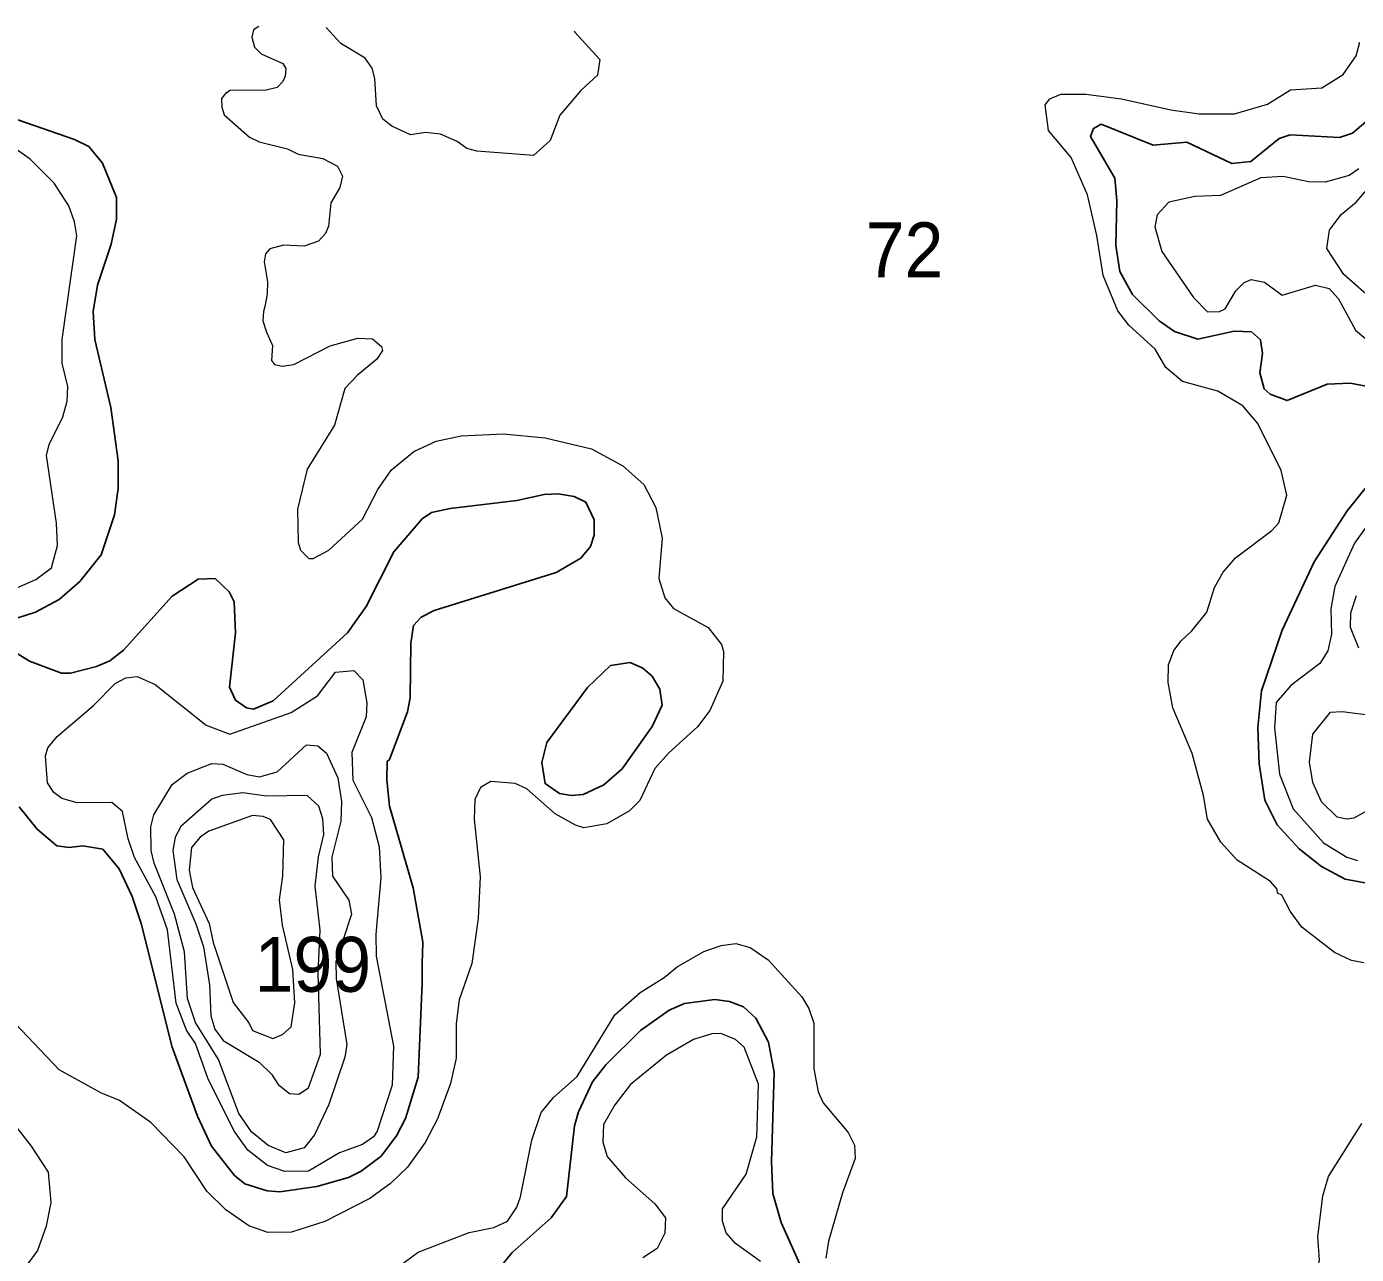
# Model space of a CAD drawing. Extents: x 673.6 to 698.9, y 7012 to 7040.1.
# Drawn here: x 680.672 to 682.608, y 7038.161 to 7039.949 of the extents above; entities that cross this region are included whole.
import ezdxf

# ---------------------------------------------------------------- set-up
doc = ezdxf.new("R2010")
doc.units = 0
doc.header["$LTSCALE"] = 0.032
doc.layers.add('1', color=7, linetype='Continuous', lineweight=25)
doc.layers.add('2', color=7, linetype='Continuous', lineweight=13)
doc.layers.add('21', color=7, linetype='Continuous')

msp = doc.modelspace()

# ---------------------------------------------------------------- linework, layer by layer
at = {"layer": '1'}
for points in [[(682.6448, 7039.8306), (682.6022, 7039.794), (682.5833, 7039.7877), (682.5115, 7039.7915), (682.4953, 7039.7862), (682.4541, 7039.7528), (682.4264, 7039.75), (682.3611, 7039.7809), (682.3119, 7039.7765), (682.2362, 7039.8072), (682.225, 7039.8009), (682.2208, 7039.7892), (682.256, 7039.7285), (682.2593, 7039.696), (682.2575, 7039.6306), (682.2632, 7039.5926), (682.2819, 7039.5593), (682.3209, 7039.5209), (682.343, 7039.5054), (682.3772, 7039.4943), (682.4301, 7039.5057), (682.455, 7039.5049), (682.4681, 7039.4934), (682.4711, 7039.4733), (682.4672, 7039.4449), (682.4735, 7039.4218), (682.4821, 7039.4142), (682.5069, 7039.4048), (682.5653, 7039.4284), (682.5987, 7039.43), (682.622, 7039.4258)], [(680.6588, 7039.0883), (680.6844, 7039.0964), (680.7189, 7039.1152), (680.7491, 7039.1411), (680.78, 7039.1802), (680.7998, 7039.2382), (680.8047, 7039.2769), (680.8047, 7039.3171), (680.7942, 7039.3948), (680.7711, 7039.4939), (680.7686, 7039.5345), (680.775, 7039.5728), (680.7948, 7039.6323), (680.8025, 7039.6691), (680.8023, 7039.7006), (680.7819, 7039.7503), (680.7624, 7039.7746), (680.7414, 7039.7851), (680.6586, 7039.8137)], [(682.6388, 7039.299), (682.5943, 7039.2441), (682.5462, 7039.17), (682.5, 7039.0702), (682.4698, 7038.9823), (682.4646, 7038.9288), (682.4664, 7038.8759), (682.4748, 7038.8229), (682.4924, 7038.7869), (682.5248, 7038.7521), (682.5571, 7038.7264), (682.5916, 7038.7077), (682.6232, 7038.7021)], [(681.2484, 7038.6162), (681.2345, 7038.6951), (681.1999, 7038.8142), (681.1959, 7038.8523), (681.1966, 7038.8793), (681.2, 7038.8823), (681.2261, 7038.9515), (681.2303, 7038.9717), (681.2312, 7039.0514), (681.235, 7039.0774), (681.2461, 7039.0891), (681.2649, 7039.0989), (681.4428, 7039.1542), (681.4785, 7039.1754), (681.4926, 7039.1922), (681.4982, 7039.2089), (681.4982, 7039.2309), (681.4858, 7039.2567), (681.4691, 7039.265), (681.4457, 7039.269), (681.4251, 7039.2681), (681.3856, 7039.2591), (681.2883, 7039.2478), (681.2613, 7039.2417), (681.2478, 7039.2323), (681.2063, 7039.1844), (681.1662, 7039.1047), (681.1389, 7039.0665), (681.0304, 7038.9673), (681.0022, 7038.9553), (680.9918, 7038.9571), (680.9757, 7038.9684), (680.9669, 7038.9872), (680.9756, 7039.0665), (680.974, 7039.1118), (680.9666, 7039.1261), (680.9464, 7039.1456), (680.9215, 7039.1449), (680.8838, 7039.1197), (680.8126, 7039.0411), (680.7929, 7039.0257), (680.7732, 7039.0175), (680.7356, 7039.008), (680.7222, 7039.0078), (680.6757, 7039.0255), (680.6577, 7039.0366)], [(680.6607, 7038.8132), (680.6869, 7038.7805), (680.7155, 7038.7566), (680.7337, 7038.7539), (680.7537, 7038.7563), (680.7824, 7038.7513), (680.8065, 7038.7231), (680.8251, 7038.6827), (680.8383, 7038.6433), (680.8834, 7038.463), (680.9204, 7038.3628), (680.9406, 7038.3188), (680.9741, 7038.2763), (680.9892, 7038.2644), (681.022, 7038.2542), (681.0405, 7038.2526), (681.0943, 7038.2602), (681.1404, 7038.2733), (681.1587, 7038.2827), (681.1879, 7038.3046), (681.2102, 7038.334)], [(681.2102, 7038.334), (681.2234, 7038.3593), (681.2419, 7038.4197), (681.2476, 7038.5565), (681.2475, 7038.5843), (681.2484, 7038.6162)], [(681.8097, 7038.1202), (681.7701, 7038.2077), (681.7583, 7038.2501), (681.7563, 7038.2961), (681.7602, 7038.4261), (681.7521, 7038.4703), (681.7332, 7038.5056), (681.7155, 7038.5219), (681.6951, 7038.5295), (681.6737, 7038.5327), (681.6297, 7038.527), (681.6071, 7038.5173), (681.5656, 7038.4873), (681.515, 7038.4377)], [(681.515, 7038.4377), (681.4956, 7038.4125), (681.475, 7038.3692), (681.4696, 7038.3487), (681.4578, 7038.2458), (681.4353, 7038.2149)], [(681.4353, 7038.2149), (681.3787, 7038.164), (681.3616, 7038.1432)]]:
    msp.add_lwpolyline(points, dxfattribs=at)
msp.add_lwpolyline([(681.5387, 7038.8686), (681.5119, 7038.845), (681.4822, 7038.8312), (681.4651, 7038.8295), (681.4474, 7038.8328), (681.4265, 7038.847), (681.4219, 7038.8779), (681.4293, 7038.9066), (681.4884, 7038.9871), (681.5217, 7039.0189), (681.5505, 7039.0233), (681.5689, 7039.0151), (681.5823, 7039.0033), (681.5937, 7038.9843), (681.5968, 7038.9612), (681.5827, 7038.9302)], close=True, dxfattribs=at)
at = {"layer": '2'}
for points in [[(681.0096, 7039.9493), (681.0019, 7039.9448), (680.9995, 7039.9337), (681.0036, 7039.9194), (681.0133, 7039.9096), (681.0445, 7039.8958), (681.0491, 7039.8884), (681.0479, 7039.8772), (681.0445, 7039.8694), (681.0364, 7039.8604), (681.0203, 7039.8568), (680.9679, 7039.8563), (680.961, 7039.852), (680.9556, 7039.8444), (680.9557, 7039.8321), (680.9595, 7039.821), (680.9963, 7039.7883), (681.0103, 7039.7813), (681.0516, 7039.7711), (681.067, 7039.7635), (681.103, 7039.7571), (681.1243, 7039.7463), (681.1316, 7039.7316), (681.1276, 7039.7152), (681.1145, 7039.6928), (681.1112, 7039.6586), (681.1069, 7039.648), (681.0966, 7039.6368), (681.0756, 7039.6298), (681.0458, 7039.631), (681.0259, 7039.6257), (681.0197, 7039.6184), (681.0176, 7039.6069), (681.0224, 7039.5777), (681.0218, 7039.5597), (681.0186, 7039.5419), (681.0165, 7039.5346), (681.0155, 7039.521), (681.0207, 7039.5042), (681.0296, 7039.485), (681.0284, 7039.4629), (681.0324, 7039.4575), (681.0439, 7039.4549), (681.0605, 7039.4571), (681.1134, 7039.4842), (681.1541, 7039.4958), (681.1753, 7039.4946), (681.1885, 7039.4836), (681.19, 7039.4778), (681.1815, 7039.465), (681.1529, 7039.4414), (681.1352, 7039.4222), (681.1201, 7039.369), (681.0799, 7039.3047), (681.0659, 7039.2466), (681.067, 7039.198), (681.0702, 7039.1869), (681.0827, 7039.1749), (681.089, 7039.1747), (681.1118, 7039.187), (681.1605, 7039.2321), (681.1832, 7039.275), (681.2029, 7039.3041), (681.2356, 7039.3308), (681.2682, 7039.3454), (681.3044, 7039.3536), (681.3658, 7039.3561), (681.4266, 7039.3503), (681.494, 7039.3344), (681.5399, 7039.3097), (681.5703, 7039.2823), (681.5879, 7039.249), (681.5968, 7039.2042), (681.592, 7039.1455), (681.6011, 7039.1174), (681.6133, 7039.102), (681.664, 7039.0745), (681.6832, 7039.0493), (681.6863, 7039.0394), (681.6856, 7038.9963), (681.6665, 7038.9533), (681.6487, 7038.9297), (681.6062, 7038.8913), (681.5862, 7038.869), (681.5644, 7038.8224), (681.5495, 7038.8075), (681.5166, 7038.7885), (681.483, 7038.7827), (681.471, 7038.7863), (681.441, 7038.8032), (681.3998, 7038.8393), (681.3832, 7038.847), (681.3475, 7038.8499), (681.3324, 7038.8411), (681.3241, 7038.8237)], [(681.4689, 7039.9428), (681.4699, 7039.9411), (681.5063, 7039.9016), (681.5031, 7039.8785), (681.4788, 7039.8561), (681.4478, 7039.8204), (681.4339, 7039.7833), (681.4095, 7039.7614), (681.327, 7039.7679), (681.3125, 7039.7716), (681.2987, 7039.7819), (681.2744, 7039.7926), (681.2525, 7039.7951), (681.2308, 7039.7918), (681.2034, 7039.8042), (681.1904, 7039.8147), (681.1812, 7039.8341), (681.1786, 7039.8739), (681.1747, 7039.8888), (681.1646, 7039.9033), (681.1293, 7039.9246), (681.1077, 7039.9479)], [(682.1548, 7039.8352), (682.1615, 7039.8441), (682.1774, 7039.8508), (682.2139, 7039.8508), (682.2658, 7039.8442), (682.3377, 7039.828), (682.3789, 7039.8221), (682.4303, 7039.8221), (682.4784, 7039.8364), (682.5118, 7039.8574), (682.5575, 7039.8599), (682.5884, 7039.8794), (682.6076, 7039.9067), (682.6124, 7039.9248), (682.6117, 7039.9264)], [(682.2394, 7039.5869), (682.2301, 7039.645), (682.2164, 7039.7041), (682.1926, 7039.7588), (682.1595, 7039.7981), (682.1548, 7039.8352)], [(680.6111, 7039.1123), (680.6851, 7039.1443), (680.7078, 7039.161), (680.7167, 7039.1935), (680.7152, 7039.226), (680.7004, 7039.3249), (680.7044, 7039.341), (680.7242, 7039.3809), (680.7309, 7039.4041), (680.7315, 7039.4252), (680.7234, 7039.4594), (680.7234, 7039.4938), (680.7446, 7039.6447), (680.7414, 7039.6651), (680.7331, 7039.6884), (680.7116, 7039.7213), (680.6768, 7039.7561), (680.6556, 7039.7713)], [(682.6115, 7039.7422), (682.5975, 7039.7324), (682.5623, 7039.7227), (682.5381, 7039.7233), (682.5015, 7039.7309), (682.4686, 7039.7293), (682.4099, 7039.7032), (682.3727, 7039.7021), (682.3349, 7039.6938), (682.3178, 7039.6753), (682.3143, 7039.6575), (682.3245, 7039.6218), (682.3705, 7039.5548), (682.3912, 7039.5338), (682.4084, 7039.5344), (682.4167, 7039.5385), (682.4325, 7039.5646), (682.4445, 7039.5768), (682.4546, 7039.5812), (682.474, 7039.5771), (682.4999, 7039.5584), (682.5482, 7039.573), (682.5684, 7039.5679), (682.5817, 7039.5528), (682.6068, 7039.5073), (682.6403, 7039.4789)], [(682.6348, 7039.5485), (682.5894, 7039.5881), (682.565, 7039.6263), (682.5685, 7039.6527), (682.5855, 7039.6758), (682.6074, 7039.6937), (682.6258, 7039.7148)], [(682.6186, 7038.586), (682.6008, 7038.5896), (682.5761, 7038.6011), (682.5285, 7038.6377), (682.5114, 7038.6612), (682.4993, 7038.6845), (682.4928, 7038.6874), (682.4924, 7038.6932), (682.4827, 7038.7045), (682.4343, 7038.7356), (682.4105, 7038.7615), (682.3909, 7038.7954), (682.3851, 7038.8296), (682.3689, 7038.891), (682.3408, 7038.9574), (682.3338, 7038.9941), (682.3341, 7039.0199), (682.3423, 7039.0407), (682.3525, 7039.0548), (682.3685, 7039.0693), (682.3899, 7039.0967), (682.4013, 7039.1323), (682.414, 7039.155), (682.432, 7039.1756), (682.4848, 7039.2156), (682.4948, 7039.2267), (682.5064, 7039.2668), (682.4984, 7039.3029), (682.4642, 7039.3715), (682.4424, 7039.3972), (682.4061, 7039.4182), (682.3545, 7039.4326), (682.3304, 7039.453), (682.3151, 7039.4794), (682.2767, 7039.5145), (682.2607, 7039.5356), (682.2394, 7039.5869)], [(682.627, 7039.2277), (682.605, 7039.1972), (682.5764, 7039.134), (682.5707, 7039.1017), (682.5715, 7039.0645), (682.5664, 7039.0403), (682.5548, 7039.0217), (682.5122, 7038.99), (682.4909, 7038.9652), (682.4884, 7038.9284), (682.4959, 7038.8609), (682.5158, 7038.8104), (682.5602, 7038.7609), (682.5942, 7038.7401), (682.6094, 7038.735)], [(682.6116, 7039.0443), (682.5993, 7039.0742), (682.5997, 7039.0955), (682.608, 7039.1209)], [(682.6293, 7038.8108), (682.6042, 7038.7966), (682.5942, 7038.795), (682.5798, 7038.7979), (682.557, 7038.8202), (682.5447, 7038.8488), (682.5395, 7038.8784), (682.5444, 7038.919), (682.5702, 7038.951), (682.587, 7038.9518), (682.6291, 7038.9466)], [(681.3241, 7038.8237), (681.3232, 7038.7952), (681.3322, 7038.711), (681.329, 7038.6504), (681.3199, 7038.5851), (681.3014, 7038.532)], [(681.2047, 7038.1373), (681.2416, 7038.1645), (681.3159, 7038.1933), (681.3517, 7038.2007), (681.372, 7038.2096), (681.3854, 7038.23), (681.391, 7038.2453), (681.4071, 7038.3276), (681.4209, 7038.3681), (681.439, 7038.3897), (681.4732, 7038.4205), (681.5283, 7038.5103), (681.5651, 7038.543), (681.6, 7038.5644), (681.6191, 7038.5802), (681.6577, 7038.6026), (681.683, 7038.611), (681.7045, 7038.6141), (681.7251, 7038.6083), (681.7514, 7038.5903), (681.8002, 7038.5366), (681.8106, 7038.5193), (681.8178, 7038.4982), (681.818, 7038.4314), (681.8244, 7038.3983), (681.8316, 7038.382), (681.8678, 7038.339), (681.8771, 7038.3205), (681.8779, 7038.301), (681.8596, 7038.251), (681.8393, 7038.1807), (681.8353, 7038.1558)], [(681.3014, 7038.532), (681.297, 7038.4977), (681.2971, 7038.4472), (681.2889, 7038.4102), (681.27, 7038.3588), (681.2519, 7038.3243), (681.226, 7038.2885), (681.2013, 7038.2645), (681.1712, 7038.2427), (681.1059, 7038.2092), (681.0574, 7038.1936), (681.023, 7038.1934), (680.9953, 7038.2032), (680.9615, 7038.2262), (680.9342, 7038.2537), (680.9008, 7038.3034), (680.8523, 7038.3536), (680.8069, 7038.3853), (680.7797, 7038.3965), (680.719, 7038.4304), (680.6548, 7038.4977)], [(681.7404, 7038.1509), (681.704, 7038.1775), (681.6904, 7038.1926), (681.6849, 7038.21), (681.685, 7038.2279), (681.7195, 7038.2785), (681.7351, 7038.3327), (681.7373, 7038.4095), (681.7166, 7038.463), (681.7037, 7038.4743), (681.6825, 7038.4833), (681.6692, 7038.4826), (681.6429, 7038.4744), (681.6034, 7038.4514), (681.5511, 7038.4089), (681.5283, 7038.379), (681.5115, 7038.3507), (681.5106, 7038.3249), (681.5169, 7038.304), (681.5437, 7038.2729), (681.5862, 7038.2353), (681.6017, 7038.2146), (681.6008, 7038.1922), (681.5898, 7038.1699), (681.5687, 7038.1563)], [(680.6459, 7038.3608), (680.6783, 7038.3189), (680.7029, 7038.281), (680.7069, 7038.237), (680.6999, 7038.2025), (680.6877, 7038.1673), (680.6475, 7038.1126)], [(682.6363, 7037.9634), (682.5866, 7037.9837), (682.5674, 7038.0007), (682.5561, 7038.0183), (682.5441, 7038.049), (682.5394, 7038.0898), (682.5435, 7038.1169), (682.5542, 7038.1532), (682.5518, 7038.1871), (682.5591, 7038.2469), (682.5675, 7038.275), (682.6158, 7038.352)]]:
    msp.add_lwpolyline(points, dxfattribs=at)
for points in [[(681.1807, 7038.5958), (681.2058, 7038.4648), (681.2041, 7038.4078), (681.1821, 7038.3408), (681.1766, 7038.3328), (681.1607, 7038.3213), (681.1271, 7038.3094), (681.0823, 7038.2826), (681.0474, 7038.282), (681.0226, 7038.2907), (680.9938, 7038.3132), (680.9742, 7038.3402), (680.9358, 7038.4167), (680.9173, 7038.4687), (680.9046, 7038.488), (680.8895, 7038.5272), (680.8769, 7038.634), (680.8597, 7038.6823), (680.8289, 7038.7393), (680.8195, 7038.7664), (680.8112, 7038.8063), (680.7958, 7038.8196), (680.7452, 7038.8188), (680.7231, 7038.8252), (680.7111, 7038.8338), (680.7022, 7038.8481), (680.6991, 7038.8873), (680.7027, 7038.899), (680.716, 7038.9157), (680.769, 7038.9606), (680.8004, 7038.9927), (680.8161, 7039.0011), (680.8326, 7039.0028), (680.8586, 7038.9915), (680.9332, 7038.932), (680.9673, 7038.9192), (681.0566, 7038.9503), (681.0953, 7038.9746), (681.1214, 7039.0094), (681.1481, 7039.0117), (681.1612, 7038.9982), (681.1672, 7038.9646), (681.1659, 7038.9443), (681.145, 7038.8924), (681.1466, 7038.8519), (681.1736, 7038.7974), (681.185, 7038.7549), (681.1876, 7038.7096), (681.1803, 7038.6275)], [(681.1222, 7038.5634), (681.1377, 7038.467), (681.1349, 7038.4486), (681.1119, 7038.3796), (681.0907, 7038.3356), (681.0758, 7038.3168), (681.0491, 7038.3093), (681.0235, 7038.32), (680.9992, 7038.3399), (680.9807, 7038.3665), (680.9512, 7038.4453), (680.9177, 7038.4993), (680.9059, 7038.5341), (680.9016, 7038.6018), (680.8868, 7038.657), (680.8575, 7038.7313), (680.8532, 7038.7494), (680.8524, 7038.7842), (680.8571, 7038.8016), (680.8836, 7038.8458), (680.9052, 7038.8624), (680.9411, 7038.8762), (680.9575, 7038.8754), (680.9922, 7038.8604), (681.0108, 7038.8567), (681.0364, 7038.8642), (681.0793, 7038.9032), (681.0959, 7038.9018), (681.1085, 7038.8912), (681.125, 7038.8556), (681.1301, 7038.8211), (681.1293, 7038.7925), (681.1162, 7038.7398), (681.117, 7038.7123), (681.1408, 7038.6773), (681.1449, 7038.6568), (681.122, 7038.5873)], [(681.0995, 7038.4531), (681.0963, 7038.5711), (681.0989, 7038.6337), (681.0916, 7038.6975), (681.0965, 7038.7402), (681.1046, 7038.7731), (681.103, 7038.7957), (681.0969, 7038.8143), (681.0799, 7038.8295), (681.0209, 7038.8287), (680.9864, 7038.8335), (680.9563, 7038.8295), (680.9413, 7038.8241), (680.8963, 7038.7844), (680.8877, 7038.769), (680.8844, 7038.7495), (680.8905, 7038.7074), (680.9181, 7038.6429), (680.929, 7038.6093), (680.9378, 7038.5541), (680.9397, 7038.509), (680.9456, 7038.4895), (680.9579, 7038.4729), (681.0104, 7038.4413), (681.028, 7038.4237), (681.0377, 7038.409), (681.0546, 7038.3956), (681.068, 7038.3948), (681.082, 7038.4042)], [(681.0444, 7038.4818), (681.0567, 7038.4929), (681.0621, 7038.5279), (681.0593, 7038.5762), (681.044, 7038.6408), (681.0398, 7038.6779), (681.0446, 7038.7128), (681.0462, 7038.7649), (681.0267, 7038.7947), (681.0161, 7038.7992), (681.0004, 7038.8006), (680.9371, 7038.7776), (680.9242, 7038.769), (680.9116, 7038.7538), (680.9083, 7038.7211), (680.9131, 7038.6958), (680.9376, 7038.6432), (680.9431, 7038.6155), (680.9726, 7038.5283), (680.9954, 7038.4986), (681.0007, 7038.4873), (681.0299, 7038.4756)]]:
    msp.add_lwpolyline(points, close=True, dxfattribs=at)

# ---------------------------------------------------------------- texts
at = {"layer": '21', "width": 0.95}
for s, p in [('72', (681.8934, 7039.5842)), ('199', (681.0037, 7038.5438))]:
    msp.add_text(s, height=0.08, dxfattribs=at).set_placement(p)

doc.saveas('drawing.dxf')
